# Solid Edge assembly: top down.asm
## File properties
Title: Yoke
Author: Deepak Maini
Template: normal.par
Last saved by: MYPC
Revision: 19
Application: Solid Edge
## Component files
u-joint.par
swivel.par
bushing1.par
ret ring.par
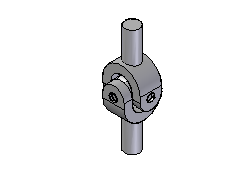
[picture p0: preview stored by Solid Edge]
